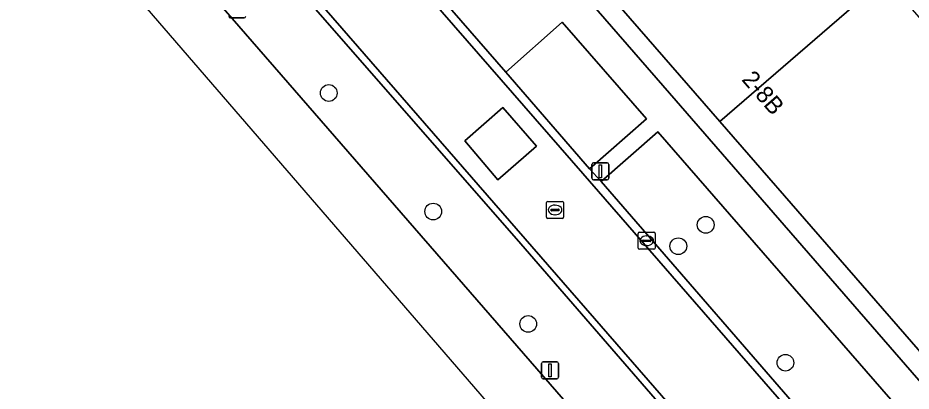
# Model space of a CAD drawing. Extents: x 155887 to 156869, y 383880 to 384678.
# Drawn here: x 156597.4 to 156649.5, y 383923.2 to 383945 of the extents above; entities that cross this region are included whole.
import ezdxf

# ---------------------------------------------------------------- set-up
doc = ezdxf.new("R2010")
doc.units = 0
for name, color, linetype in [('IMGEO_Berm_groen', 7, 'Continuous'), ('IMGEO_Boom', 7, 'Continuous'), ('IMGEO_Kolk', 7, 'Continuous'), ('IMGEO_Lichtmast', 7, 'Continuous'), ('IMGEO_OVBaan_gesloten', 7, 'Continuous'), ('IMGEO_Pand', 7, 'Continuous'), ('IMGEO_Pand_nummerreeks', 7, 'Continuous'), ('IMGEO_Parkeervlak_open', 7, 'Continuous'), ('IMGEO_Rijbaan_lokaal_gesloten', 7, 'Continuous'), ('IMGEO_Rijbaan_lokaal_open', 7, 'Continuous'), ('IMGEO_Rioolput', 7, 'Continuous'), ('IMGEO_Voetpad_open', 7, 'Continuous')]:
    doc.layers.add(name, color=color, linetype=linetype)

msp = doc.modelspace()

# ---------------------------------------------------------------- linework, layer by layer
at = {"layer": 'IMGEO_Berm_groen'}
for points in [[(156562.118, 384000), (156634.845, 383916.306), (156649.574, 383899.314), (156657.48, 383890.128), (156660.479, 383886.538), (156661.73, 383884.973), (156667.165, 383889.242), (156667.519, 383889.539)], [(156646.315, 383909.821), (156646.375, 383909.933), (156646.206, 383910.051), (156645.847, 383909.788), (156626.506, 383932.134), (156601.837, 383960.361), (156567.837, 383999.499)]]:
    msp.add_lwpolyline(points, dxfattribs=at)
at = {"layer": 'IMGEO_Boom'}
for centre in [(156615.549, 383940.645), (156621.648, 383933.718), (156637.556, 383932.942), (156635.957, 383931.693), (156627.194, 383927.152), (156642.208, 383924.887)]:
    msp.add_circle(centre, 0.489, dxfattribs=at)
at = {"layer": 'IMGEO_Kolk'}
for p, q in [((156633.61, 383931.586), (156633.61, 383932.438)), ((156633.685, 383932.512), (156634.537, 383932.512)), ((156634.098, 383932.292), (156634.123, 383932.292)), ((156634.611, 383932.438), (156634.611, 383931.586)), ((156633.869, 383932.006), (156633.869, 383932.018)), ((156634.307, 383931.969), (156633.909, 383931.969)), ((156633.912, 383932.055), (156634.31, 383932.055)), ((156634.121, 383931.732), (156634.096, 383931.732)), ((156634.353, 383932.018), (156634.353, 383932.006)), ((156634.537, 383931.512), (156633.685, 383931.512))]:
    msp.add_line(p, q, dxfattribs=at)
for points in [[(156633.61, 383931.586), (156633.61, 383932.438)], [(156633.685, 383932.512), (156634.537, 383932.512)], [(156634.611, 383932.438), (156634.611, 383931.586)], [(156634.537, 383931.512), (156633.685, 383931.512)]]:
    msp.add_lwpolyline(points, dxfattribs=at)
for centre, radius, start, end in [((156633.687, 383932.436), 0.0765, 91.552, 178.448), ((156633.687, 383932.436), 0.0765, 91.552, 178.448), ((156634.535, 383932.436), 0.0765, 1.552, 88.448), ((156634.535, 383932.436), 0.0765, 1.552, 88.448), ((156633.687, 383931.588), 0.0765, 181.552, 268.448), ((156633.687, 383931.588), 0.0765, 181.552, 268.448), ((156633.909, 383932.015), 0.0403, 85.8775, 175.7526), ((156633.906, 383932.005), 0.0366, 178.938, 274.7102), ((156634.31, 383932.012), 0.043, 264.8664, 352.4533), ((156634.314, 383932.017), 0.0386, 1.7309, 96.639), ((156634.535, 383931.588), 0.0765, 271.552, 358.448), ((156634.535, 383931.588), 0.0765, 271.552, 358.448)]:
    msp.add_arc(centre, radius, start, end, dxfattribs=at)
for centre, major_axis, ratio, start_param, end_param in [((156634.097, 383932.012), (-0.387, 0.002), 0.722429, 4.712389, 7.853982), ((156634.122, 383932.012), (-0.39, 0.002), 0.717154, 1.570796, 4.712389)]:
    msp.add_ellipse(centre, major_axis=major_axis, ratio=ratio, start_param=start_param, end_param=end_param, dxfattribs=at)
at = {"layer": 'IMGEO_Lichtmast'}
for p, q in [((156610.606, 383945.035), (156609.816, 383945.035)), ((156609.816, 383945.035), (156610.606, 383945.035)), ((156630.91, 383935.669), (156630.91, 383936.469)), ((156630.91, 383936.469), (156630.91, 383935.669)), ((156631.01, 383936.569), (156631.8, 383936.569)), ((156631.8, 383936.569), (156631.01, 383936.569)), ((156631.9, 383936.469), (156631.9, 383935.669)), ((156631.9, 383935.669), (156631.9, 383936.469)), ((156631.8, 383935.569), (156631.01, 383935.569)), ((156631.01, 383935.569), (156631.8, 383935.569)), ((156627.971, 383924.043), (156627.971, 383924.843)), ((156627.971, 383924.843), (156627.971, 383924.043)), ((156628.071, 383924.943), (156628.861, 383924.943)), ((156628.861, 383924.943), (156628.071, 383924.943)), ((156628.961, 383924.843), (156628.961, 383924.043)), ((156628.961, 383924.043), (156628.961, 383924.843)), ((156628.861, 383923.943), (156628.071, 383923.943)), ((156628.071, 383923.943), (156628.861, 383923.943))]:
    msp.add_line(p, q, dxfattribs=at)
for points in [[(156631.33, 383936.444), (156631.48, 383936.444), (156631.48, 383935.694), (156631.33, 383935.694), (156631.33, 383936.444)], [(156628.391, 383924.818), (156628.541, 383924.818), (156628.541, 383924.068), (156628.391, 383924.068), (156628.391, 383924.818)]]:
    msp.add_lwpolyline(points, dxfattribs=at)
for centre, start, end in [((156609.816, 383945.135), 180, 270), ((156609.816, 383945.135), 180, 270), ((156610.606, 383945.135), 270, 0), ((156610.606, 383945.135), 270, 0), ((156631.01, 383936.469), 90, 180), ((156631.01, 383936.469), 90, 180), ((156631.8, 383936.469), 0, 90), ((156631.8, 383936.469), 360, 90), ((156631.01, 383935.669), 180, 270), ((156631.01, 383935.669), 180, 270), ((156631.8, 383935.669), 270, 0), ((156631.8, 383935.669), 270, 0), ((156628.071, 383924.843), 90, 180), ((156628.071, 383924.843), 90, 180), ((156628.861, 383924.843), 0, 90), ((156628.861, 383924.843), 360, 90), ((156628.071, 383924.043), 180, 270), ((156628.071, 383924.043), 180, 270), ((156628.861, 383924.043), 270, 0), ((156628.861, 383924.043), 270, 0)]:
    msp.add_arc(centre, 0.1, start, end, dxfattribs=at)
at = {"layer": 'IMGEO_OVBaan_gesloten'}
msp.add_lwpolyline([(156500, 384061.368), (156513.218, 384046.155), (156516.017, 384048.538), (156657.549, 383884.637), (156660.479, 383886.538), (156657.48, 383890.128), (156649.574, 383899.314), (156634.845, 383916.306), (156562.118, 384000), (156526.643, 384040.832), (156517.145, 384051.764), (156500, 384071.498)], dxfattribs=at)
at = {"layer": 'IMGEO_Pand'}
for points in [[(156648.049, 383947.354), (156634.828, 383962.561), (156625.17, 383954.192), (156638.385, 383938.981)], [(156661.304, 383932.108), (156648.049, 383947.354), (156638.385, 383938.981), (156651.646, 383923.717)]]:
    msp.add_lwpolyline(points, close=True, dxfattribs=at)
at = {"layer": 'IMGEO_Parkeervlak_open'}
for points in [[(156625.882, 383941.86), (156630.78, 383936.216), (156634.101, 383939.133), (156629.17, 383944.785)], [(156631.453, 383935.472), (156645.025, 383919.822), (156648.363, 383922.735), (156634.764, 383938.382)]]:
    msp.add_lwpolyline(points, close=True, dxfattribs=at)
at = {"layer": 'IMGEO_Rijbaan_lokaal_gesloten'}
for points in [[(156504.298, 384073.374), (156520.535, 384054.614), (156527.288, 384046.812), (156528.598, 384045.292), (156528.617, 384045.27), (156530.033, 384043.663), (156567.998, 384000), (156646.206, 383910.051), (156646.375, 383909.933), (156646.315, 383909.821)], [(156650.086, 383913.301), (156630.384, 383935.946), (156605.883, 383964.081), (156603.554, 383966.725), (156574.636, 384000), (156565.483, 384010.532), (156529.628, 384051.804)]]:
    msp.add_lwpolyline(points, dxfattribs=at)
msp.add_lwpolyline([(156625.718, 383939.791), (156627.676, 383937.541), (156625.42, 383935.576), (156623.489, 383937.842)], close=True, dxfattribs=at)
at = {"layer": 'IMGEO_Rijbaan_lokaal_open'}
for points in [[(156530.033, 384043.663), (156529.694, 384043.376), (156567.401, 384000), (156567.837, 383999.499), (156601.837, 383960.361), (156626.506, 383932.134), (156645.847, 383909.788), (156646.206, 383910.051), (156567.998, 384000)], [(156625.42, 383935.576), (156627.676, 383937.541), (156625.718, 383939.791), (156623.489, 383937.842)]]:
    msp.add_lwpolyline(points, close=True, dxfattribs=at)
msp.add_lwpolyline([(156650.441, 383913.603), (156645.704, 383919.064), (156645.025, 383919.822), (156631.453, 383935.472), (156630.78, 383936.216), (156625.882, 383941.86), (156618.912, 383949.885), (156606.226, 383964.383), (156605.883, 383964.081), (156630.384, 383935.946), (156650.086, 383913.301)], dxfattribs=at)
at = {"layer": 'IMGEO_Rioolput'}
for p, q in [((156628.259, 383933.386), (156628.259, 383934.238)), ((156628.334, 383934.312), (156629.186, 383934.312)), ((156629.26, 383934.238), (156629.26, 383933.386)), ((156628.518, 383933.806), (156628.518, 383933.818)), ((156628.956, 383933.769), (156628.558, 383933.769)), ((156628.561, 383933.855), (156628.959, 383933.855)), ((156628.747, 383934.092), (156628.772, 383934.092)), ((156629.002, 383933.818), (156629.002, 383933.806)), ((156629.186, 383933.312), (156628.334, 383933.312)), ((156628.77, 383933.532), (156628.745, 383933.532))]:
    msp.add_line(p, q, dxfattribs=at)
for points in [[(156628.259, 383933.386), (156628.259, 383934.238)], [(156628.334, 383934.312), (156629.186, 383934.312)], [(156629.26, 383934.238), (156629.26, 383933.386)], [(156629.186, 383933.312), (156628.334, 383933.312)]]:
    msp.add_lwpolyline(points, dxfattribs=at)
for centre, radius, start, end in [((156628.336, 383934.236), 0.0765, 91.552, 178.448), ((156628.336, 383934.236), 0.0765, 91.552, 178.448), ((156629.184, 383934.236), 0.0765, 1.552, 88.448), ((156629.184, 383934.236), 0.0765, 1.552, 88.448), ((156628.558, 383933.815), 0.0403, 85.8775, 175.7526), ((156628.555, 383933.805), 0.0366, 178.938, 274.7102), ((156628.959, 383933.812), 0.043, 264.8664, 352.4533), ((156628.963, 383933.817), 0.0386, 1.7309, 96.639), ((156628.336, 383933.388), 0.0765, 181.552, 268.448), ((156628.336, 383933.388), 0.0765, 181.552, 268.448), ((156629.184, 383933.388), 0.0765, 271.552, 358.448), ((156629.184, 383933.388), 0.0765, 271.552, 358.448)]:
    msp.add_arc(centre, radius, start, end, dxfattribs=at)
for centre, major_axis, ratio, start_param, end_param in [((156628.746, 383933.812), (-0.387, 0.002), 0.722429, 4.712389, 7.853982), ((156628.771, 383933.812), (-0.39, 0.002), 0.717154, 1.570796, 4.712389)]:
    msp.add_ellipse(centre, major_axis=major_axis, ratio=ratio, start_param=start_param, end_param=end_param, dxfattribs=at)
at = {"layer": 'IMGEO_Voetpad_open'}
for points in [[(156635.435, 383940.644), (156662.111, 383909.928), (156664.695, 383908.697), (156651.646, 383923.717), (156638.385, 383938.981), (156625.17, 383954.192), (156611.955, 383969.403), (156611.103, 383968.653)], [(156635.435, 383940.644), (156611.103, 383968.653), (156609.604, 383967.363), (156622.22, 383952.787), (156618.912, 383949.885), (156625.882, 383941.86), (156629.17, 383944.785), (156634.101, 383939.133), (156630.78, 383936.216), (156631.453, 383935.472), (156634.764, 383938.382), (156648.363, 383922.735), (156649.012, 383921.996), (156656.543, 383913.299), (156654.022, 383911.101), (156665.453, 383904.527), (156666.298, 383906.852), (156664.695, 383908.697), (156662.111, 383909.928)]]:
    msp.add_lwpolyline(points, close=True, dxfattribs=at)

# ---------------------------------------------------------------- texts
at = {"layer": 'IMGEO_Pand_nummerreeks'}
msp.add_text('2-8B', height=1, rotation=310.9835, dxfattribs=at).set_placement((156639.615, 383941.407))

doc.saveas('drawing.dxf')
